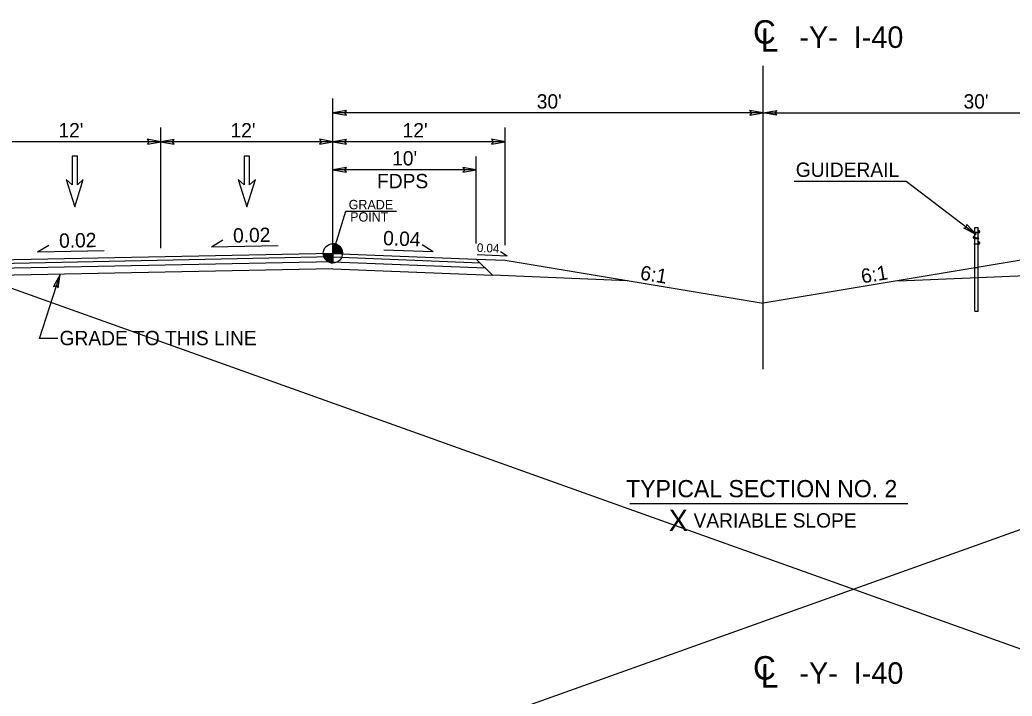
# Model space of a CAD drawing. Extents: x 1553195 to 1553792, y 810516 to 810787.
# Drawn here: x 1553492.4 to 1553561.6, y 810562.7 to 810609.9 of the extents above; entities that cross this region are included whole.
import ezdxf

# ---------------------------------------------------------------- set-up
doc = ezdxf.new("R2010")
doc.units = 0
for name, color, linetype in [('Old_Level_11', 7, 'Continuous'), ('Prop Dimension', 7, 'Continuous'), ('Prop DSN Text', 7, 'Continuous'), ('Prop Pavement Schedule Description CELL', 7, 'Continuous'), ('Prop Shade Light', 7, 'Continuous'), ('Prop Typical Section', 7, 'Continuous'), ('Sheet Sticker Incomplete CELL', 7, 'Continuous'), ('Typical Arrow Superelevation CELL', 7, 'Continuous'), ('Typical Pavement Slope CELL', 7, 'Continuous'), ('Typical Text Centerline CELL', 7, 'Continuous'), ('Typical Text Grade Point CELL', 7, 'Continuous'), ('Typical Text ID Circle CELL', 7, 'Continuous'), ('z - Construction', 7, 'Continuous')]:
    doc.layers.add(name, color=color, linetype=linetype)

msp = doc.modelspace()

# ---------------------------------------------------------------- linework, layer by layer
at = {"layer": 'Old_Level_11'}
for p, q in [((1553514.206, 810593.587), (1553514.206, 810594.258)), ((1553513.535, 810593.587), (1553514.206, 810593.587)), ((1553514.205, 810592.916), (1553514.206, 810593.587)), ((1553514.206, 810593.587), (1553514.205, 810592.916)), ((1553514.878, 810593.587), (1553514.206, 810593.587))]:
    msp.add_line(p, q, dxfattribs=at)
for points in [[(1553514.212, 810594.258), (1553514.212, 810594.258), (1553514.212, 810593.587)], [(1553514.226, 810594.258), (1553514.226, 810593.587)], [(1553514.239, 810594.257), (1553514.239, 810593.587)], [(1553514.253, 810594.257), (1553514.253, 810593.587)], [(1553514.266, 810594.255), (1553514.266, 810593.587)], [(1553514.28, 810594.254), (1553514.28, 810593.587)], [(1553514.293, 810594.252), (1553514.293, 810593.587)], [(1553514.306, 810594.251), (1553514.306, 810593.587)], [(1553514.32, 810594.249), (1553514.32, 810593.587)], [(1553514.333, 810594.246), (1553514.333, 810593.587)], [(1553514.347, 810594.243), (1553514.347, 810593.587)], [(1553514.36, 810594.24), (1553514.36, 810593.587)], [(1553514.374, 810594.237), (1553514.374, 810593.587)], [(1553514.387, 810594.233), (1553514.387, 810593.587)], [(1553514.4, 810594.23), (1553514.4, 810593.587)], [(1553514.414, 810594.225), (1553514.414, 810593.587)], [(1553514.427, 810594.221), (1553514.427, 810593.587)], [(1553514.441, 810594.217), (1553514.441, 810593.587)], [(1553514.454, 810594.211), (1553514.454, 810593.587)], [(1553514.468, 810594.205), (1553514.468, 810593.587)], [(1553514.481, 810594.199), (1553514.481, 810593.587)], [(1553514.494, 810594.193), (1553514.494, 810593.587)], [(1553514.508, 810594.187), (1553514.508, 810593.587)], [(1553514.521, 810594.179), (1553514.521, 810593.587)], [(1553514.535, 810594.172), (1553514.535, 810593.587)], [(1553514.548, 810594.164), (1553514.548, 810593.587)], [(1553514.562, 810594.157), (1553514.562, 810593.587)], [(1553514.575, 810594.148), (1553514.575, 810593.587)], [(1553514.588, 810594.139), (1553514.588, 810593.587)], [(1553514.602, 810594.129), (1553514.602, 810593.587)], [(1553514.615, 810594.12), (1553514.615, 810593.587)], [(1553514.629, 810594.109), (1553514.629, 810593.587)], [(1553514.642, 810594.097), (1553514.642, 810593.587)], [(1553514.655, 810594.085), (1553514.655, 810593.587)], [(1553514.669, 810594.073), (1553514.669, 810593.587)], [(1553514.682, 810594.06), (1553514.682, 810593.587)], [(1553514.696, 810594.046), (1553514.696, 810593.587)], [(1553514.709, 810594.032), (1553514.709, 810593.587)], [(1553514.723, 810594.015), (1553514.723, 810593.587)], [(1553514.736, 810593.999), (1553514.736, 810593.587)], [(1553514.75, 810593.981), (1553514.75, 810593.587)], [(1553513.538, 810593.587), (1553513.538, 810593.514)], [(1553513.551, 810593.587), (1553513.551, 810593.435)], [(1553513.565, 810593.587), (1553513.565, 810593.387)], [(1553513.578, 810593.587), (1553513.578, 810593.347)], [(1553513.592, 810593.587), (1553513.592, 810593.315)], [(1553513.605, 810593.587), (1553513.605, 810593.287)], [(1553513.619, 810593.587), (1553513.619, 810593.262)], [(1553513.632, 810593.587), (1553513.632, 810593.238)], [(1553513.645, 810593.587), (1553513.645, 810593.217)], [(1553513.659, 810593.587), (1553513.659, 810593.198)], [(1553513.672, 810593.587), (1553513.672, 810593.18)], [(1553513.686, 810593.587), (1553513.686, 810593.163)], [(1553513.699, 810593.587), (1553513.699, 810593.147)], [(1553513.713, 810593.587), (1553513.713, 810593.132)], [(1553513.726, 810593.587), (1553513.726, 810593.117)], [(1553513.739, 810593.587), (1553513.739, 810593.104)], [(1553513.753, 810593.587), (1553513.753, 810593.092)], [(1553513.766, 810593.587), (1553513.766, 810593.08)], [(1553513.78, 810593.587), (1553513.78, 810593.068)], [(1553513.793, 810593.587), (1553513.793, 810593.057)], [(1553513.807, 810593.587), (1553513.807, 810593.047)], [(1553513.82, 810593.587), (1553513.82, 810593.038)], [(1553513.833, 810593.587), (1553513.833, 810593.029)], [(1553513.847, 810593.587), (1553513.847, 810593.02)], [(1553513.86, 810593.587), (1553513.86, 810593.011)], [(1553513.874, 810593.587), (1553513.874, 810593.004)], [(1553513.887, 810593.587), (1553513.887, 810592.996)], [(1553513.901, 810593.587), (1553513.901, 810592.989)], [(1553513.914, 810593.587), (1553513.914, 810592.983)], [(1553513.927, 810593.587), (1553513.927, 810592.977)], [(1553513.941, 810593.587), (1553513.941, 810592.971)], [(1553513.954, 810593.587), (1553513.954, 810592.965)], [(1553513.968, 810593.587), (1553513.968, 810592.959)], [(1553513.981, 810593.587), (1553513.981, 810592.954)], [(1553513.995, 810593.587), (1553513.995, 810592.95)], [(1553514.008, 810593.587), (1553514.008, 810592.945)], [(1553514.021, 810593.587), (1553514.021, 810592.942)], [(1553514.035, 810593.587), (1553514.035, 810592.938)], [(1553514.048, 810593.587), (1553514.048, 810592.935)], [(1553514.062, 810593.587), (1553514.062, 810592.932)], [(1553514.075, 810593.587), (1553514.075, 810592.929)], [(1553514.089, 810593.587), (1553514.089, 810592.926)], [(1553514.102, 810593.587), (1553514.102, 810592.925)], [(1553514.115, 810593.587), (1553514.115, 810592.922)], [(1553514.129, 810593.587), (1553514.129, 810592.92)], [(1553514.142, 810593.587), (1553514.142, 810592.919)], [(1553514.156, 810593.587), (1553514.156, 810592.917)], [(1553514.169, 810593.587), (1553514.169, 810592.917)], [(1553514.183, 810593.587), (1553514.183, 810592.916)], [(1553514.196, 810593.587), (1553514.196, 810592.916), (1553514.196, 810592.916)], [(1553514.763, 810593.961), (1553514.763, 810593.587)], [(1553514.776, 810593.941), (1553514.776, 810593.587)], [(1553514.79, 810593.918), (1553514.79, 810593.587)], [(1553514.803, 810593.894), (1553514.803, 810593.587)], [(1553514.817, 810593.866), (1553514.817, 810593.587)], [(1553514.83, 810593.835), (1553514.83, 810593.587)], [(1553514.843, 810593.797), (1553514.843, 810593.587)], [(1553514.857, 810593.751), (1553514.857, 810593.587)], [(1553514.87, 810593.682), (1553514.87, 810593.587)]]:
    msp.add_lwpolyline(points, dxfattribs=at)
msp.add_circle((1553514.206, 810593.587), 0.671, dxfattribs=at)
for start, end in [(359.99048, 89.99048), (179.99048, 269.99048)]:
    msp.add_arc((1553514.206, 810593.587), 0.671, start, end, dxfattribs=at)
at = {"layer": 'Prop Dimension'}
for p, q in [((1553493.608, 810593.69), (1553494.391, 810594.163)), ((1553505.739, 810594.051), (1553506.522, 810594.524)), ((1553505.739, 810594.051), (1553510.4, 810594.144)), ((1553521.206, 810593.683), (1553520.433, 810594.172)), ((1553493.608, 810593.69), (1553498.268, 810593.783)), ((1553521.206, 810593.683), (1553517.756, 810593.821)), ((1553526.345, 810593.402), (1553524.275, 810593.484)), ((1553526.345, 810593.402), (1553525.881, 810593.695))]:
    msp.add_line(p, q, dxfattribs=at)
at = {"layer": 'Prop DSN Text'}
for points in [[(1553515.143, 810603.547), (1553514.206, 810603.386), (1553515.148, 810603.219), (1553515.028, 810603.386)], [(1553543.268, 810603.224), (1553544.206, 810603.386), (1553543.263, 810603.552), (1553543.383, 810603.386)], [(1553545.143, 810603.224), (1553544.206, 810603.386), (1553545.148, 810603.552), (1553545.028, 810603.386)], [(1553501.268, 810601.212), (1553502.206, 810601.374), (1553501.263, 810601.54), (1553501.383, 810601.374)], [(1553503.143, 810601.535), (1553502.206, 810601.374), (1553503.148, 810601.207), (1553503.028, 810601.374)], [(1553513.268, 810601.212), (1553514.206, 810601.374), (1553513.263, 810601.54), (1553513.383, 810601.374)], [(1553515.143, 810601.535), (1553514.206, 810601.374), (1553515.148, 810601.207), (1553515.028, 810601.374)], [(1553525.268, 810601.212), (1553526.206, 810601.374), (1553525.263, 810601.54), (1553525.383, 810601.374)], [(1553515.143, 810599.579), (1553514.206, 810599.418), (1553515.148, 810599.251), (1553515.028, 810599.418)], [(1553523.268, 810599.257), (1553524.206, 810599.418), (1553523.263, 810599.585), (1553523.383, 810599.418)], [(1553558.402, 810595.602), (1553559.05, 810594.905), (1553558.199, 810595.344), (1553558.395, 810595.404)], [(1553495.046, 810591.181), (1553495.179, 810592.123), (1553494.732, 810591.277), (1553494.927, 810591.34)]]:
    msp.add_lwpolyline(points, close=True, dxfattribs=at)
at = {"layer": 'Prop Pavement Schedule Description CELL'}
for p, q in [((1553493.738, 810587.64), (1553495.179, 810592.123)), ((1553495.021, 810587.64), (1553493.738, 810587.64)), ((1553534.903, 810576.154), (1553554.304, 810576.154))]:
    msp.add_line(p, q, dxfattribs=at)
at = {"layer": 'Prop Typical Section'}
msp.add_line((1553544.206, 810585.508), (1553544.206, 810606.674), dxfattribs=at)
for points in [[(1553496.799, 810598.748), (1553496.393, 810598.373), (1553496.393, 810600.374), (1553496.018, 810600.374), (1553496.018, 810598.373), (1553495.612, 810598.748), (1553496.206, 810596.842)], [(1553496.799, 810598.748), (1553496.393, 810598.373), (1553496.393, 810600.374), (1553496.018, 810600.374), (1553496.018, 810598.373), (1553495.612, 810598.748), (1553496.206, 810596.842)], [(1553508.799, 810598.748), (1553508.393, 810598.373), (1553508.393, 810600.374), (1553508.018, 810600.374), (1553508.018, 810598.373), (1553507.612, 810598.748), (1553508.206, 810596.842)], [(1553508.799, 810598.748), (1553508.393, 810598.373), (1553508.393, 810600.374), (1553508.018, 810600.374), (1553508.018, 810598.373), (1553507.612, 810598.748), (1553508.206, 810596.842)]]:
    msp.add_lwpolyline(points, close=True, dxfattribs=at)
at = {"layer": 'Sheet Sticker Incomplete CELL'}
for p, q in [((1553524.206, 810593.187), (1553526.206, 810593.107)), ((1553526.206, 810593.107), (1553544.206, 810590.107)), ((1553562.206, 810593.107), (1553544.206, 810590.107)), ((1553534.758, 810591.682), (1553525.334, 810592.059)), ((1553553.653, 810591.682), (1553563.077, 810592.059))]:
    msp.add_line(p, q, dxfattribs=at)
at = {"layer": 'Typical Arrow Superelevation CELL'}
for p, q in [((1553652.472, 810606.601), (1553448.543, 810533.73)), ((1553448.543, 810606.601), (1553652.472, 810533.73))]:
    msp.add_line(p, q, dxfattribs=at)
at = {"layer": 'Typical Pavement Slope CELL'}
for p, q in [((1553514.206, 810593.587), (1553490.206, 810593.107)), ((1553514.206, 810593.337), (1553490.206, 810592.857)), ((1553514.206, 810593.587), (1553524.206, 810593.187)), ((1553514.206, 810593.337), (1553524.466, 810592.927)), ((1553514.206, 810593.004), (1553490.206, 810592.524)), ((1553514.206, 810593.004), (1553524.813, 810592.579)), ((1553524.206, 810593.187), (1553525.334, 810592.059)), ((1553514.206, 810592.504), (1553490.206, 810592.024)), ((1553514.206, 810592.504), (1553525.334, 810592.059))]:
    msp.add_line(p, q, dxfattribs=at)
at = {"layer": 'Typical Text Centerline CELL'}
for p, q in [((1553558.956, 810589.565), (1553558.956, 810595.399)), ((1553558.956, 810595.399), (1553559.206, 810595.399)), ((1553559.206, 810589.565), (1553559.206, 810595.399)), ((1553558.919, 810595.029), (1553558.919, 810595.055)), ((1553558.919, 810595.055), (1553559.242, 810595.055)), ((1553559.242, 810595.029), (1553558.919, 810595.029)), ((1553558.95, 810594.789), (1553558.919, 810594.789)), ((1553558.919, 810594.763), (1553558.95, 810594.763)), ((1553559.242, 810594.659), (1553558.919, 810594.659)), ((1553558.95, 810594.763), (1553558.95, 810594.789)), ((1553559.211, 810595.159), (1553559.211, 810595.185)), ((1553559.211, 810595.185), (1553559.242, 810595.185)), ((1553559.242, 810595.159), (1553559.211, 810595.159)), ((1553559.242, 810594.633), (1553559.242, 810594.659)), ((1553558.919, 810594.633), (1553559.242, 810594.633)), ((1553558.919, 810594.237), (1553558.919, 810594.263)), ((1553558.919, 810594.263), (1553559.242, 810594.263)), ((1553559.242, 810594.237), (1553558.919, 810594.237)), ((1553559.211, 810594.368), (1553559.211, 810594.394)), ((1553559.211, 810594.394), (1553559.242, 810594.394)), ((1553559.242, 810594.368), (1553559.211, 810594.368)), ((1553558.956, 810589.565), (1553559.206, 810589.565))]:
    msp.add_line(p, q, dxfattribs=at)
for centre in [(1553558.914, 810594.711), (1553559.247, 810595.107), (1553559.247, 810594.315)]:
    msp.add_circle(centre, 0.0416, dxfattribs=at)
for centre, radius, start, end in [((1553558.919, 810594.711), 0.0781, 90, 270), ((1553558.919, 810594.711), 0.0521, 90, 270), ((1553559.242, 810595.107), 0.0781, 270, 90), ((1553559.242, 810595.107), 0.0521, 270, 90), ((1553559.242, 810594.315), 0.0781, 270, 90), ((1553559.242, 810594.315), 0.0521, 270, 90)]:
    msp.add_arc(centre, radius, start, end, dxfattribs=at)
at = {"layer": 'Typical Text Grade Point CELL'}
msp.add_line((1553558.956, 810592.607), (1553559.206, 810592.607), dxfattribs=at)
at = {"layer": 'Typical Text ID Circle CELL'}
msp.add_lwpolyline([(1553514.206, 810593.587), (1553515.109, 810596.541), (1553518.647, 810596.541)], dxfattribs=at)
at = {"layer": 'z - Construction'}
for p, q in [((1553514.206, 810594.276), (1553514.206, 810604.376)), ((1553544.206, 810603.386), (1553514.206, 810603.386)), ((1553544.206, 810603.386), (1553574.206, 810603.386)), ((1553502.206, 810593.951), (1553502.206, 810602.374)), ((1553526.206, 810594.159), (1553526.206, 810602.374)), ((1553502.206, 810601.374), (1553490.206, 810601.374)), ((1553514.206, 810601.374), (1553502.206, 810601.374)), ((1553526.206, 810601.374), (1553514.206, 810601.374)), ((1553524.206, 810594.276), (1553524.206, 810600.332)), ((1553524.206, 810599.418), (1553514.206, 810599.418))]:
    msp.add_line(p, q, dxfattribs=at)
msp.add_lwpolyline([(1553546.36, 810598.62), (1553554.171, 810598.62), (1553559.05, 810594.905)], dxfattribs=at)

# ---------------------------------------------------------------- texts
at = {"layer": 'Prop Pavement Schedule Description CELL'}
for s, height, p in [('-Y-  I-40', 1.5, (1553546.736, 810607.917)), ("30'", 1, (1553528.419, 810603.686)), ("30'", 1, (1553558.179, 810603.686)), ("12'", 1, (1553495.068, 810601.674)), ("12'", 1, (1553507.068, 810601.674)), ("12'", 1, (1553519.068, 810601.674)), ("10'", 1, (1553518.338, 810599.718)), ('GUIDERAIL', 1, (1553546.48, 810598.921)), ('FDPS', 1, (1553517.286, 810598.129)), ('GRADE TO THIS LINE', 1, (1553495.147, 810587.183)), ('TYPICAL SECTION NO. 2', 1.2, (1553534.654, 810576.58)), ('X', 1.5, (1553537.623, 810574.219)), ('VARIABLE SLOPE', 1, (1553539.351, 810574.464)), ('-Y-  I-40', 1.5, (1553546.736, 810563.569))]:
    msp.add_text(s, height=height, dxfattribs=at).set_placement(p)
for s, height, rotation, p in [('0.02', 1, 1.14587, (1553507.253, 810594.334)), ('0.02', 1, 1.14587, (1553495.122, 810593.973)), ('0.04', 1, 357.70939, (1553517.693, 810594.166)), ('0.04', 0.6, 357.70939, (1553524.237, 810593.692)), ('6:1', 1, 350.53768, (1553535.582, 810591.772)), ('6:1', 1, 9.46232, (1553551.116, 810591.486))]:
    msp.add_text(s, height=height, rotation=rotation, dxfattribs=at).set_placement(p)
at = {"layer": 'Prop Shade Light'}
for p in [(1553543.503, 810608.208), (1553543.503, 810563.861)]:
    msp.add_text('C', height=1.64, dxfattribs=at).set_placement(p)
for p in [(1553544.048, 810607.648), (1553544.048, 810563.301)]:
    msp.add_text('L', height=1.641, rotation=359.9469, dxfattribs=at).set_placement(p)
at = {"layer": 'Typical Text Grade Point CELL'}
msp.add_text('GROUND LINE', height=0.01, dxfattribs=at).set_placement((1553559.024, 810592.609))
at = {"layer": 'Typical Text ID Circle CELL'}
for s, p in [('GRADE', (1553515.306, 810596.663)), ('POINT', (1553515.409, 810595.805))]:
    msp.add_text(s, height=0.6525, dxfattribs=at).set_placement(p)

doc.saveas('drawing.dxf')
